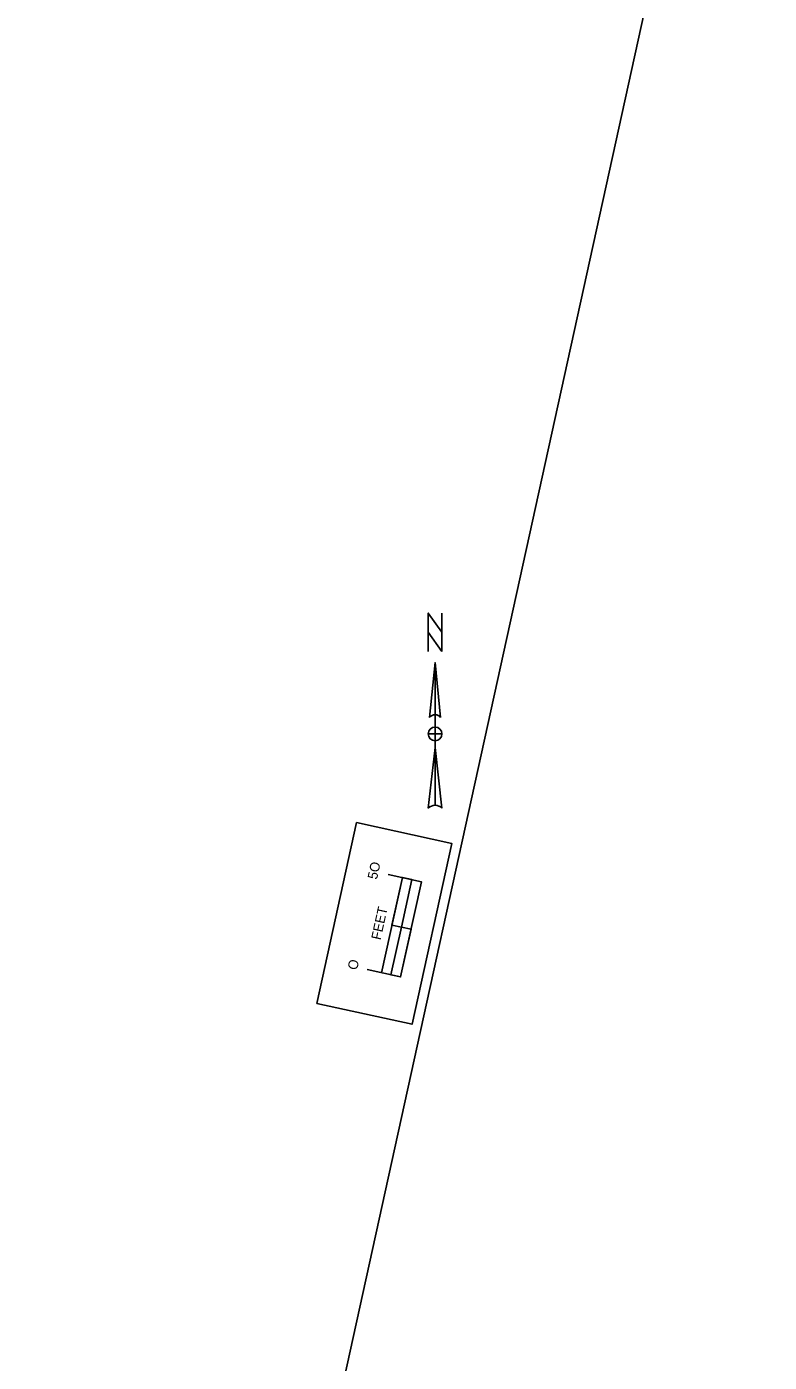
# Model space of a CAD drawing. Extents: x 14104283 to 14121738, y 8635219 to 8671666.
# Drawn here: x 14108432 to 14108813, y 8640210 to 8640895 of the extents above; entities that cross this region are included whole.
import ezdxf

# ---------------------------------------------------------------- set-up
doc = ezdxf.new("R2010")
doc.units = 0
for name, color, linetype in [('dsnCellsNorthArrow', 7, 'Continuous'), ('dsnCellsScaleBlock', 7, 'Continuous'), ('dsnNonPlotable', 7, 'Continuous')]:
    doc.layers.add(name, color=color, linetype=linetype)

msp = doc.modelspace()

# ---------------------------------------------------------------- linework, layer by layer
at = {"layer": 'dsnCellsNorthArrow'}
for p, q in [((14108641.86, 8640569.29), (14108644.67, 8640541.12)), ((14108641.86, 8640569.29), (14108641.86, 8640496.05)), ((14108639.04, 8640541.12), (14108639.04, 8640541.12)), ((14108639.15, 8640541.38), (14108639.67, 8640541.97)), ((14108638.34, 8640494.64), (14108641.86, 8640525.63)), ((14108641.86, 8640529.15), (14108641.86, 8640529.15))]:
    msp.add_line(p, q, dxfattribs=at)
msp.add_lwpolyline([(14108645.38, 8640574.93), (14108638.34, 8640584.79), (14108638.34, 8640594.65), (14108645.38, 8640584.79)], close=True, dxfattribs=at)
for points in [[(14108638.34, 8640574.93), (14108638.34, 8640594.65), (14108645.38, 8640584.79), (14108645.38, 8640594.65)], [(14108639.04, 8640541.12), (14108641.86, 8640569.29), (14108641.86, 8640542.53)], [(14108641.86, 8640529.15), (14108641.86, 8640532.67), (14108638.34, 8640532.67)], [(14108645.38, 8640532.67), (14108641.86, 8640532.67), (14108641.86, 8640536.19)], [(14108641.86, 8640496.05), (14108641.86, 8640525.63), (14108645.38, 8640494.64)]]:
    msp.add_lwpolyline(points, dxfattribs=at)
for centre, radius, start, end in [((14108641.86, 8640539.01), 3.52, 90.02039, 143.12574), ((14108641.86, 8640539.01), 3.52, 36.84806, 90.02184), ((14108641.86, 8640532.67), 3.52, 90, 180), ((14108641.86, 8640532.67), 3.52, 180, 270), ((14108641.86, 8640532.67), 3.52, 0, 90), ((14108641.86, 8640532.67), 3.52, 270, 360), ((14108641.86, 8640490.95), 5.1, 89.98939, 133.61895), ((14108641.86, 8640490.94), 5.11, 46.40206, 90.00064)]:
    msp.add_arc(centre, radius, start, end, dxfattribs=at)
at = {"layer": 'dsnCellsScaleBlock'}
msp.add_line((14108629.49, 8640432.47), (14108619.72, 8640434.62), dxfattribs=at)
msp.add_line((14108629.49, 8640432.47), (14108619.72, 8640434.62), dxfattribs=at)
for points in [[(14108630.04, 8640383.72), (14108581.2, 8640394.45), (14108601.59, 8640487.23), (14108650.42, 8640476.5)], [(14108581.2, 8640394.45), (14108601.59, 8640487.23), (14108650.42, 8640476.5), (14108630.04, 8640383.72)], [(14108630.04, 8640383.72), (14108581.2, 8640394.45), (14108601.59, 8640487.23), (14108650.42, 8640476.5)], [(14108624.57, 8640433.55), (14108629.93, 8640457.97), (14108625.08, 8640459.04), (14108619.72, 8640434.62)], [(14108624.12, 8640408.05), (14108629.49, 8640432.47), (14108624.57, 8640433.55), (14108619.2, 8640409.13)]]:
    msp.add_lwpolyline(points, close=True, dxfattribs=at)
for points in [[(14108607.03, 8640411.81), (14108624.12, 8640408.05), (14108634.85, 8640456.89), (14108617.76, 8640460.64)], [(14108614.35, 8640410.2), (14108625.08, 8640459.04)]]:
    msp.add_lwpolyline(points, dxfattribs=at)
at = {"layer": 'dsnNonPlotable'}
msp.add_lwpolyline([(14107490.45, 8639880.3), (14107826.84, 8641411.28), (14108813.31, 8641194.53), (14108476.92, 8639663.55)], close=True, dxfattribs=at)

# ---------------------------------------------------------------- texts
at = {"layer": 'dsnCellsScaleBlock'}
for s, p in [('5O', (14108612, 8640457.74)), ('FEET', (14108613.88, 8640426.71)), ('O', (14108601.79, 8640411.29))]:
    msp.add_text(s, height=5, rotation=77.60784, dxfattribs=at).set_placement(p)

doc.saveas('drawing.dxf')
